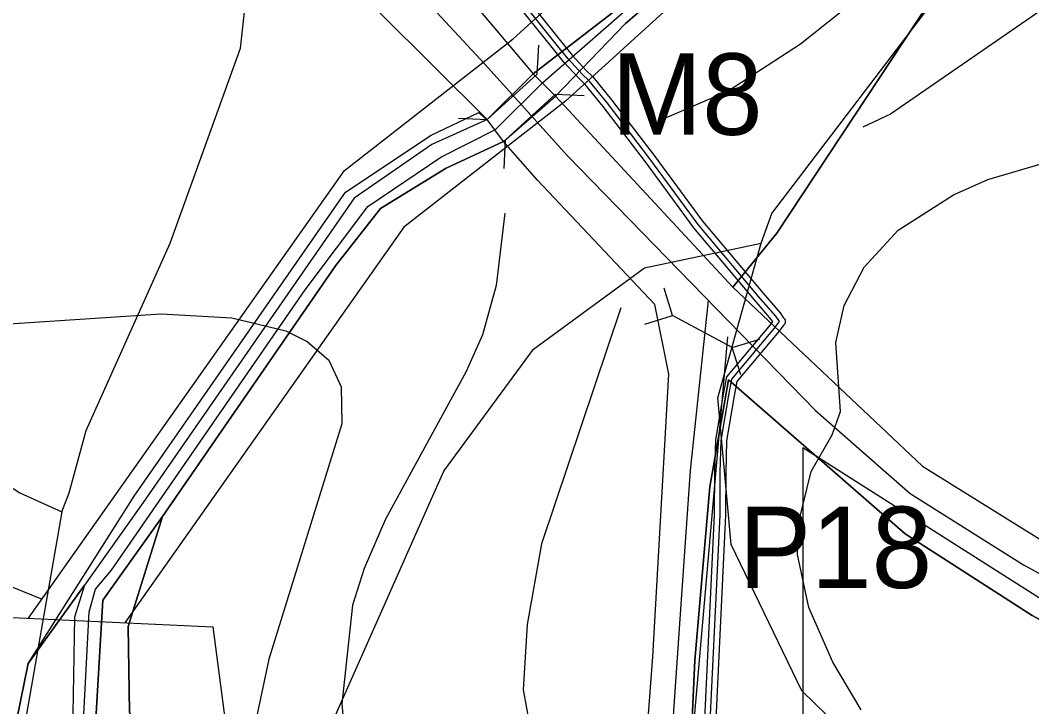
# Model space of a CAD drawing. Extents: x -662500 to -653478, y -1056827 to -1049993.
# Drawn here: x -660170.7 to -659984.1, y -1053039.4 to -1052912.9 of the extents above; entities that cross this region are included whole.
import ezdxf

# ---------------------------------------------------------------- set-up
doc = ezdxf.new("R2010")
doc.units = 0
for name, color, linetype in [('63LINIE', 7, 'Continuous'), ('Vrstva 11', 7, 'Continuous'), ('Vrstva 17', 7, 'Continuous'), ('Vrstva 24', 7, 'Continuous'), ('Vrstva 32', 7, 'Continuous'), ('Vrstva 37', 7, 'Continuous'), ('Vrstva 42', 7, 'Continuous'), ('Vrstva 47', 7, 'Continuous'), ('Vrstva 5', 7, 'Continuous'), ('Vrstva 50', 7, 'Continuous'), ('Vrstva 51', 7, 'Continuous'), ('Vrstva 57', 7, 'Continuous'), ('Vrstva 6', 7, 'Continuous'), ('Vrstva 61', 7, 'Continuous'), ('Vrstva 7', 7, 'Continuous')]:
    doc.layers.add(name, color=color, linetype=linetype)

# ---------------------------------------------------------------- blocks, each defined once
blk = doc.blocks.new('PSZ021')
at = {"layer": 'Vrstva 17'}
for points in [[(-10.01, 6.26), (-6.26, 2.51), (6.24, 2.51), (9.99, 6.26)], [(-10.01, -6.24), (-6.26, -2.49), (6.24, -2.49), (9.99, -6.24)]]:
    blk.add_lwpolyline(points, dxfattribs=at)

msp = doc.modelspace()

# ---------------------------------------------------------------- linework, layer by layer
at = {"layer": '63LINIE'}
msp.add_lwpolyline([(-660279.97, -1052761.03), (-660274.18, -1052772.81), (-660267.41, -1052780.76), (-660257, -1052789.21), (-660195.64, -1052822), (-660171, -1052837.21), (-660163.83, -1052841.24), (-660157.65, -1052847.13), (-660132.52, -1052869.51), (-660111.66, -1052892.24), (-660084.95, -1052921), (-660069.74, -1052937.89), (-660023.99, -1052984.81), (-660006.51, -1053000.13), (-659985.6, -1053013.28), (-659850.42, -1053086.91), (-659781.9, -1053123.24), (-659710.72, -1053161.03), (-659675.58, -1053176.35), (-659546.48, -1053229.26), (-659428.67, -1053277.07), (-659332.46, -1053315.26), (-659288.19, -1053334.01)], dxfattribs=at)
at = {"layer": 'Vrstva 11'}
msp.add_lwpolyline([(-660043.77, -1052964.52), (-660047.11, -1052995.9), (-660048.8, -1053020.58), (-660051.61, -1053061.61), (-660052.93, -1053079.39), (-660057.59, -1053114.8), (-660060.88, -1053162.14), (-660061.5, -1053172.08), (-660065.23, -1053196.24), (-660068.52, -1053209.73), (-660080.33, -1053244.37), (-660088.5, -1053263.64), (-660096.4, -1053281.22), (-660102.08, -1053296.45), (-660104.3, -1053303.24), (-660111.19, -1053332.15), (-660115.89, -1053363.94), (-660119.67, -1053410.57), (-660121.55, -1053443.11), (-660128.59, -1053535.41), (-660141.02, -1053666.13)], dxfattribs=at)
at = {"layer": 'Vrstva 24'}
for points in [[(-660034, -1052954), (-660032, -1052948.5), (-660000, -1052906.38), (-659983, -1052884), (-659923.5, -1052843.5), (-659891.5, -1052807.5), (-659876.5, -1052780.5), (-659868, -1052749), (-659871, -1052717.5), (-659880, -1052690.5), (-659893, -1052641), (-659893, -1052609.5), (-659864.5, -1052533), (-659861.5, -1052506), (-659866.5, -1052474.5), (-659880.5, -1052438.5), (-659901.5, -1052398), (-659927, -1052348.5), (-659940, -1052302)], [(-660163, -1053003.5), (-660161.64, -1053000), (-660158.5, -1052988.5), (-660143, -1052954), (-660130, -1052918), (-660126.5, -1052886.5), (-660132, -1052865)], [(-660331, -1053241.5), (-660301, -1053212), (-660278, -1053198), (-660227.5, -1053179), (-660190.5, -1053163), (-660174, -1053153.5), (-660166, -1053148.5), (-660158, -1053138.5), (-660146, -1053116.5), (-660094.29, -1053000), (-660092.5, -1052996), (-660076, -1052973.5), (-660055.5, -1052958.5), (-660034, -1052954)], [(-659728.49, -1053235.51), (-659755.5, -1053223.5), (-659901.5, -1053140), (-659970.5, -1053087.5), (-659990.5, -1053068), (-660000, -1053060.67), (-660008, -1053054.5), (-660026.5, -1053036.5), (-660039.5, -1053009.5), (-660040.38, -1053000), (-660042, -1052982.5), (-660034, -1052954)], [(-660322, -1052973), (-660298, -1052967.5), (-660263, -1052966), (-660228, -1052971.5), (-660198.5, -1052982), (-660170.72, -1053000), (-660163, -1053003.5)], [(-660163, -1053003.5), (-660174, -1053066.5), (-660178.5, -1053074), (-660183, -1053084.5), (-660192.5, -1053091.5), (-660213.5, -1053095), (-660260.5, -1053096.5), (-660299, -1053106), (-660322, -1053122.5), (-660356.5, -1053167.5), (-660401, -1053208), (-660418.5, -1053226), (-660434.5, -1053237.5)]]:
    msp.add_lwpolyline(points, dxfattribs=at)
at = {"layer": 'Vrstva 32'}
msp.add_lwpolyline([(-660160.88, -1053125.12), (-660160.66, -1053117.41), (-660159.16, -1053045.6), (-660157.94, -1053021.94), (-660156.76, -1053017.77), (-660153.81, -1053014.23), (-660118.13, -1052962.6), (-660106.54, -1052947.23), (-660093.09, -1052938.1), (-660082.98, -1052933), (-660074.25, -1052924.36), (-660055.79, -1052908.21), (-660043.52, -1052897.56), (-659991.83, -1052849.55), (-659971.21, -1052829.43), (-659940.88, -1052799.92), (-659928.36, -1052782.89), (-659895.08, -1052736.55)], dxfattribs=at)
at = {"layer": 'Vrstva 37'}
msp.add_lwpolyline([(-660026.32, -1052991.73), (-660026.32, -1053058.37), (-660035.43, -1053154.64), (-660050.23, -1053231.54), (-659773.69, -1053361.27), (-659704.27, -1053171.81), (-659884.58, -1053081.65)], close=True, dxfattribs=at)
at = {"layer": 'Vrstva 42'}
for p, q in [((-660065.77, -1052923.99), (-660066.99, -1052922.81)), ((-660065.71, -1052924.04), (-660065.77, -1052923.99)), ((-660039.42, -1052979.02), (-660031.5, -1052969.65)), ((-660039.93, -1052981.98), (-660039.42, -1052979.02))]:
    msp.add_line(p, q, dxfattribs=at)
for points in [[(-660071.79, -1052917.29), (-660078.98, -1052908.26), (-660085.4, -1052901.23), (-660088.54, -1052898.23), (-660097.28, -1052891.36), (-660097.88, -1052890.86), (-660113.54, -1052878.01), (-660128.62, -1052862.3), (-660142.63, -1052848.21), (-660154.25, -1052838.33), (-660171.42, -1052826.63), (-660193.06, -1052813.87), (-660215.92, -1052802.12), (-660236.98, -1052791.1), (-660257.23, -1052778.77), (-660267.65, -1052767.16), (-660272.2, -1052758.2)], [(-660066.99, -1052922.81), (-660069.6, -1052919.97), (-660071.79, -1052917.29)], [(-660030.72, -1052968.24), (-660031.28, -1052967.46), (-660034.46, -1052963.79), (-660045.6, -1052950.52), (-660054.52, -1052938.4), (-660062.35, -1052928.19), (-660065.71, -1052924.04)], [(-660031.5, -1052969.65), (-660030.58, -1052968.43), (-660030.72, -1052968.24)], [(-660088.15, -1053276.4), (-660075.09, -1053253.54), (-660063.07, -1053219.83), (-660055.85, -1053184.99), (-660053.25, -1053160.83), (-660052.11, -1053157.3), (-660050.97, -1053154.4), (-660049.97, -1053151.48), (-660047.52, -1053138.32), (-660046.36, -1053113.18), (-660046.14, -1053108.29), (-660045.22, -1053082.55), (-660044.35, -1053062.53), (-660041.58, -1053004.07), (-660041.53, -1052996.23), (-660041.37, -1052990.33), (-660039.93, -1052981.98)]]:
    msp.add_lwpolyline(points, dxfattribs=at)
at = {"layer": 'Vrstva 47'}
for points in [[(-660045.35, -1053062.49), (-660042.58, -1053004.04), (-660042.53, -1052996.21), (-660042.37, -1052990.23), (-660040.91, -1052981.8), (-660040.35, -1052978.59), (-660032.28, -1052969.03), (-660031.82, -1052968.42), (-660032.06, -1052968.08), (-660035.22, -1052964.44), (-660046.39, -1052951.13), (-660055.32, -1052939), (-660063.14, -1052928.8), (-660066.45, -1052924.72), (-660066.46, -1052924.71), (-660067.7, -1052923.51), (-660070.36, -1052920.63), (-660072.57, -1052917.92), (-660079.74, -1052908.91)], [(-660078.21, -1052907.61), (-660071.02, -1052916.67), (-660068.85, -1052919.31), (-660066.27, -1052922.11), (-660065.07, -1052923.27), (-660064.97, -1052923.36), (-660061.57, -1052927.57), (-660053.72, -1052937.8), (-660044.82, -1052949.9), (-660033.7, -1052963.15), (-660030.5, -1052966.84), (-660029.91, -1052967.65), (-660029.77, -1052967.84), (-660029.58, -1052968.1), (-660029.58, -1052968.76), (-660029.78, -1052969.03), (-660030.72, -1052970.28), (-660038.48, -1052979.46), (-660038.94, -1052982.15), (-660040.37, -1052990.43), (-660040.53, -1052996.24), (-660040.58, -1053004.1), (-660043.35, -1053062.58)]]:
    msp.add_lwpolyline(points, dxfattribs=at)
at = {"layer": 'Vrstva 5'}
for points in [[(-659991.81, -1052751.6), (-660010.37, -1052780.75), (-660015.6, -1052789.79), (-660018.46, -1052799.22), (-660019.99, -1052823.38), (-660022.81, -1052832.29), (-660031.02, -1052842.56), (-660031.73, -1052843.45), (-660064, -1052875.84), (-660076.7, -1052884.94), (-660092.72, -1052891.64), (-660101.87, -1052893.05), (-660096.81, -1052898.11), (-660076.02, -1052922.76), (-660060.79, -1052911.01), (-660049.28, -1052900.52), (-660021.37, -1052875.26), (-659983.56, -1052839.55), (-659948.71, -1052805.54), (-659940.23, -1052796.79), (-659929.58, -1052782.17), (-659896.18, -1052735.72)], [(-659893.7, -1052737.91), (-659927.06, -1052783.51), (-659937.57, -1052798.73), (-659946.56, -1052807.92), (-659980.71, -1052840.86), (-660019.16, -1052877.46), (-660047.02, -1052903.13), (-660059.01, -1052913.47), (-660071.92, -1052926.88), (-660039.24, -1052962.1), (-660031.07, -1052952.12), (-659995.64, -1052898.4), (-659986.59, -1052886.79), (-659977.95, -1052879.73), (-659969.58, -1052873.81), (-659937.32, -1052850.73), (-659918.06, -1052840.85), (-659913.38, -1052838.57), (-659906.2, -1052834), (-659900.19, -1052829.18), (-659884.49, -1052800.77), (-659878.28, -1052777.87), (-659865.78, -1052739.54)], [(-659865.78, -1052739.54), (-659878.28, -1052777.87), (-659884.49, -1052800.77), (-659900.19, -1052829.18), (-659906.2, -1052834), (-659913.38, -1052838.57), (-659937.32, -1052850.73), (-659969.58, -1052873.81), (-659986.59, -1052886.79), (-659995.64, -1052898.4), (-660031.07, -1052952.12), (-660039.24, -1052962.1), (-660004.2, -1052995.1), (-659978.55, -1053011.07), (-659877.72, -1053065.47), (-659795.26, -1053109.44)], [(-660065.03, -1053172.38), (-660064.33, -1053133.08), (-660064.14, -1053121.91), (-660060.42, -1053103.31), (-660057.71, -1053079.73), (-660053.97, -1053030.21), (-660051.01, -1052978.13), (-660053.61, -1052965.27), (-660075.23, -1052942.33), (-660081.53, -1052935.22), (-660084.53, -1052931.2), (-660114.36, -1052901.46), (-660145.01, -1052867.3), (-660170.48, -1052845.46), (-660192.36, -1052831.33), (-660221.62, -1052816.23), (-660262.56, -1052793.72), (-660278.43, -1052777.59), (-660290.42, -1052757.76)], [(-660273.35, -1052758.76), (-660266.1, -1052772.64), (-660257.07, -1052781.78), (-660245.2, -1052788.96), (-660217.62, -1052803.21), (-660182.01, -1052822.13), (-660158.75, -1052836.98), (-660138.02, -1052855.02), (-660101.87, -1052893.05), (-660096.81, -1052898.11), (-660076.02, -1052922.76), (-660071.92, -1052926.88), (-660039.24, -1052962.1), (-660004.2, -1052995.1), (-659978.55, -1053011.07), (-659877.72, -1053065.47), (-659795.26, -1053109.44)], [(-660114.36, -1052901.46), (-660084.53, -1052931.2), (-660094.75, -1052935.76), (-660109.05, -1052945.68), (-660148.01, -1053001.78), (-660158.78, -1053017), (-660169.18, -1053031.47), (-660175.58, -1053062.54), (-660176.15, -1053079.57), (-660175.03, -1053103.15), (-660182.71, -1053108.71), (-660215.4, -1053107.5), (-660282.8, -1053101.97), (-660299.37, -1053101.45), (-660321.32, -1053100.08), (-660331.11, -1053100.8), (-660334.08, -1053069.39), (-660337.24, -1053041.34), (-660347, -1052992.85), (-660348.28, -1052977.44), (-660347.13, -1052959.14), (-660343.22, -1052929.09), (-660339.77, -1052916.82), (-660337.19, -1052902.25)], [(-660060.79, -1052911.01), (-660076.02, -1052922.76), (-660084.53, -1052931.2), (-660094.75, -1052935.76), (-660109.05, -1052945.68), (-660148.01, -1053001.78), (-660158.78, -1053017), (-660160.63, -1053022.92), (-660161.37, -1053065.69), (-660162.29, -1053124.36), (-660159.28, -1053125.93), (-660158.13, -1053065.76), (-660155.45, -1053019.8), (-660144.4, -1053004.38), (-660112.49, -1052958.14), (-660104.22, -1052947.56), (-660092.12, -1052940.17), (-660081.53, -1052935.22), (-660071.92, -1052926.88), (-660059.01, -1052913.47), (-660047.02, -1052903.13)], [(-660126.59, -1053589.2), (-660118.91, -1053503.44), (-660111.89, -1053403.2), (-660108.8, -1053372.46), (-660103.38, -1053346.8), (-660096.52, -1053301.66), (-660093.7, -1053289.88), (-660091, -1053284.32), (-660083.08, -1053260.59), (-660074.85, -1053238.74), (-660066.72, -1053215.08), (-660061.35, -1053195.73), (-660057.3, -1053173.33), (-660052.73, -1053144.83), (-660051.02, -1053123.63), (-660048.41, -1053079.23), (-660046.22, -1053030.94), (-660043.45, -1052998.9), (-660040.02, -1052979.17), (-660007.4, -1053007.56), (-659984.03, -1053022.62), (-659883.53, -1053077.01), (-659802.22, -1053120.51), (-659716.54, -1053165.89)], [(-659716.54, -1053165.89), (-659802.22, -1053120.51), (-659883.53, -1053077.01), (-659984.03, -1053022.62), (-660007.4, -1053007.56), (-660040.02, -1052979.17), (-660043.45, -1052998.9), (-660046.22, -1053030.94), (-660048.41, -1053079.23), (-660051.02, -1053123.63), (-660052.73, -1053144.83), (-660057.3, -1053173.33), (-660061.35, -1053195.73), (-660066.72, -1053215.08), (-660074.85, -1053238.74), (-660083.08, -1053260.59), (-660091, -1053284.32), (-660093.7, -1053289.88), (-660096.52, -1053301.66), (-660103.38, -1053346.8), (-660108.8, -1053372.46), (-660111.89, -1053403.2), (-660118.91, -1053503.44), (-660126.59, -1053589.2)]]:
    msp.add_lwpolyline(points, dxfattribs=at)
for points in [[(-660081.53, -1052935.22), (-660092.12, -1052940.17), (-660104.22, -1052947.56), (-660112.49, -1052958.14), (-660144.4, -1053004.38), (-660150.73, -1053024.65), (-660150.51, -1053040.43), (-660144.36, -1053055.57), (-660133.37, -1053072.12), (-660130.34, -1053089.39), (-660124.45, -1053106.32), (-660085.27, -1053118.51), (-660064.14, -1053121.91), (-660060.42, -1053103.31), (-660057.71, -1053079.73), (-660053.97, -1053030.21), (-660051.01, -1052978.13), (-660053.61, -1052965.27), (-660075.23, -1052942.33)], [(-660144.4, -1053004.38), (-660155.45, -1053019.8), (-660158.13, -1053065.76), (-660159.28, -1053125.93), (-660158.67, -1053133.25), (-660133.92, -1053118.5), (-660134.88, -1053146.27), (-660130.49, -1053145.54), (-660111.34, -1053139.03), (-660077.5, -1053133.38), (-660064.33, -1053133.08), (-660064.14, -1053121.91), (-660085.27, -1053118.51), (-660124.45, -1053106.32), (-660130.34, -1053089.39), (-660133.37, -1053072.12), (-660144.36, -1053055.57), (-660150.51, -1053040.43), (-660150.73, -1053024.65)], [(-660158.78, -1053017), (-660160.63, -1053022.92), (-660161.37, -1053065.69), (-660162.29, -1053124.36), (-660173.45, -1053120.87), (-660175.03, -1053103.15), (-660176.15, -1053079.57), (-660175.58, -1053062.54), (-660169.18, -1053031.47)]]:
    msp.add_lwpolyline(points, close=True, dxfattribs=at)
at = {"layer": 'Vrstva 50'}
msp.add_lwpolyline([(-660435.07, -1052998.4), (-660338.47, -1052921.22), (-660327.47, -1053057.73), (-660321.24, -1053097.21), (-660175.03, -1053103.15), (-660174.83, -1053022.87), (-660135.14, -1053024.72), (-660124.45, -1053106.32), (-660064.14, -1053121.91), (-660064.92, -1053137.67), (-660124.48, -1053141.31), (-660143.9, -1053158.22), (-660224.98, -1053182.72), (-660282.65, -1053206.04), (-660302.63, -1053225.87), (-660408.17, -1053286.14), (-660457.22, -1053301.47), (-660422.63, -1053240.33), (-660404.5, -1053207.93), (-660439.36, -1053118.83)], close=True, dxfattribs=at)
at = {"layer": 'Vrstva 51'}
for points in [[(-660169.13, -1053023.13), (-660110.85, -1052940.58), (-660079.74, -1052916.29), (-659950.2, -1052798.66), (-659898.58, -1052720.65), (-659915.89, -1052669.98), (-659910.89, -1052596.38), (-659900.42, -1052552.71), (-659942.19, -1052387.83), (-659921.6, -1052399.48), (-659893.5, -1052409.43), (-659785.78, -1052462.16), (-659600.37, -1052554.27), (-659621.1, -1052589.25), (-659403.17, -1052709.23)], [(-659408.68, -1052722.85), (-659645.22, -1052595.6), (-659623.64, -1052558.85), (-659899.32, -1052423.28), (-659921, -1052417.16), (-659884.97, -1052552.61), (-659896.01, -1052598.65), (-659902.05, -1052660.61), (-659882, -1052722.78), (-659938.73, -1052808.5), (-660070.07, -1052927.77), (-660099.87, -1052951.04), (-660151.35, -1053023.96)]]:
    msp.add_lwpolyline(points, dxfattribs=at)
at = {"layer": 'Vrstva 57'}
msp.add_lwpolyline([(-660289.6, -1052768.03), (-660283.97, -1052827.25), (-660271.76, -1052869.38), (-660260.42, -1052899.71), (-660230.86, -1052987.03), (-660197.02, -1053007.24), (-660166.62, -1053019.58)], dxfattribs=at)
at = {"layer": 'Vrstva 6'}
msp.add_lwpolyline([(-660169.18, -1053031.47), (-660149.65, -1053000.64), (-660110.69, -1052944.54), (-660094.85, -1052934.08), (-660086.09, -1052929.89), (-660084.53, -1052931.2), (-660094.75, -1052935.76), (-660109.05, -1052945.68), (-660148.01, -1053001.78), (-660158.78, -1053017)], close=True, dxfattribs=at)
at = {"layer": 'Vrstva 61'}
for points in [[(-660055.43, -1052968.88), (-660050.35, -1052967.33), (-660051.9, -1052962.25)], [(-660039.32, -1052973.2), (-660050.35, -1052967.33)], [(-660040.21, -1052971.27), (-660052.48, -1053111.57), (-660057.25, -1053166.08), (-660064.24, -1053210.94), (-660077.54, -1053248.19), (-660090.91, -1053279.88), (-660093.08, -1053291.6)], [(-660037.77, -1052978.27), (-660039.32, -1052973.2), (-660034.25, -1052971.65)]]:
    msp.add_lwpolyline(points, dxfattribs=at)
at = {"layer": 'Vrstva 7'}
for p, q in [((-659962.39, -1052897.3), (-660010.15, -1052930.18)), ((-660019.22, -1052911.33), (-660026.73, -1052917.28)), ((-660026.73, -1052917.28), (-660040.05, -1052925.93)), ((-660040.05, -1052925.93), (-660053.08, -1052931.52)), ((-660010.15, -1052930.18), (-660015.25, -1052932.59)), ((-659992.15, -1052942.23), (-659951.9, -1052930.32)), ((-659998.53, -1052945.06), (-659992.15, -1052942.23)), ((-660008.73, -1052951.58), (-659998.53, -1052945.06)), ((-660081.29, -1052948.44), (-660082.85, -1052961.78)), ((-660014.97, -1052958.38), (-660008.73, -1052951.58)), ((-660018.65, -1052965.47), (-660014.97, -1052958.38)), ((-660082.85, -1052961.78), (-660085.4, -1052970.85)), ((-660059.89, -1052965.89), (-660074.49, -1053009.4)), ((-660020.21, -1052972.27), (-660018.65, -1052965.47)), ((-660172.7, -1052968.87), (-660144.64, -1052967.03)), ((-660144.64, -1052967.03), (-660131.6, -1052967.74)), ((-660131.6, -1052967.74), (-660121.68, -1052970.14)), ((-660121.68, -1052970.14), (-660117.71, -1052972.13)), ((-660117.71, -1052972.13), (-660113.74, -1052975.53)), ((-660085.4, -1052970.85), (-660088.38, -1052977.66)), ((-660019.36, -1052985.02), (-660020.21, -1052972.27)), ((-660113.74, -1052975.53), (-660111.47, -1052980.49)), ((-660088.38, -1052977.66), (-660103.26, -1053004.86)), ((-660111.47, -1052980.49), (-660111.33, -1052987.29)), ((-660020.92, -1052989.28), (-660019.36, -1052985.02)), ((-660111.33, -1052987.29), (-660124.8, -1053030.66)), ((-660024.74, -1052996.08), (-660020.92, -1052989.28)), ((-660027.15, -1053005.86), (-660024.74, -1052996.08)), ((-660103.26, -1053004.86), (-660107.22, -1053013.93)), ((-660027.3, -1053011.38), (-660027.15, -1053005.86)), ((-660074.49, -1053009.4), (-660077.18, -1053024.28)), ((-660025.17, -1053021.16), (-660027.3, -1053011.38)), ((-660107.22, -1053013.93), (-660109.35, -1053020.74)), ((-660109.35, -1053020.74), (-660111.33, -1053038.88)), ((-660020.78, -1053031.22), (-660025.17, -1053021.16)), ((-660077.18, -1053024.28), (-660077.89, -1053036.33)), ((-660124.8, -1053030.66), (-660128.2, -1053046.53)), ((-660015.53, -1053040.01), (-660020.78, -1053031.22)), ((-660077.89, -1053036.33), (-660076.05, -1053046.25)), ((-660111.33, -1053038.88), (-660110.48, -1053047.95))]:
    msp.add_line(p, q, dxfattribs=at)

# ---------------------------------------------------------------- block references
at = {"layer": 'Vrstva 17', "rotation": 42.265730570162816}
msp.add_blockref('PSZ021', (-660078.21, -1052928.84), dxfattribs=at)

# ---------------------------------------------------------------- texts
at = {"layer": 'Vrstva 17'}
msp.add_text('M8', height=15, rotation=360, dxfattribs=at).set_placement((-660061.59, -1052933.99))
at = {"layer": 'Vrstva 61'}
msp.add_text('P18', height=15, dxfattribs=at).set_placement((-660038.14, -1053017.55))

doc.saveas('drawing.dxf')
